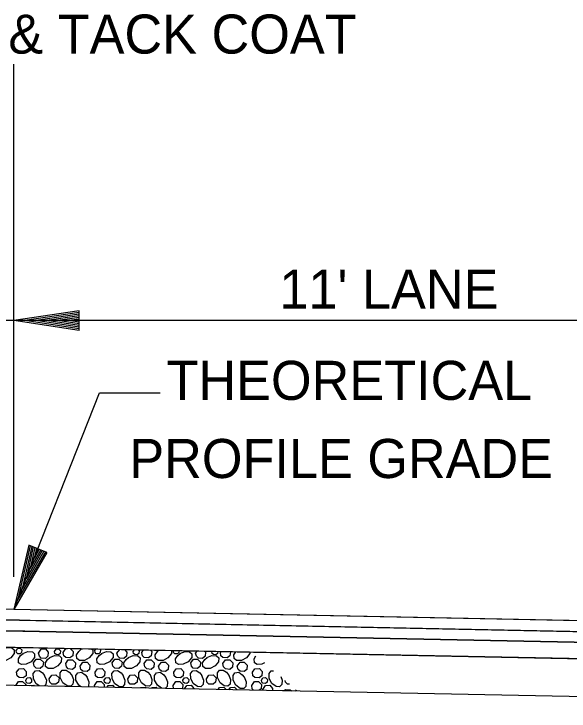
# Model space of a CAD drawing. Extents: x 2478 to 3210, y 439 to 841.
# Drawn here: x 2627.54 to 2644.6, y 587.29 to 608.7 of the extents above; entities that cross this region are included whole.
import ezdxf

# ---------------------------------------------------------------- set-up
doc = ezdxf.new("R2010")
doc.units = 0
for name, color, linetype in [('19', 7, 'Continuous'), ('R_Annotation', 7, 'Continuous'), ('R_Centerline', 7, 'Continuous'), ('R_Dimension', 7, 'Continuous')]:
    doc.layers.add(name, color=color, linetype=linetype)

msp = doc.modelspace()

# ---------------------------------------------------------------- linework, layer by layer
at = {"layer": '19'}
for points in [[(2601.503, 590.935), (2601.338, 590.605), (2605.378, 590.524), (2627.711, 590.078), (2649.713, 589.634), (2653.713, 589.474), (2653.543, 589.814), (2649.543, 589.974), (2627.543, 590.414)], [(2605.378, 590.524), (2605.212, 590.194), (2649.879, 589.301), (2649.713, 589.634)], [(2605.212, 590.194), (2604.965, 589.699), (2650.132, 588.796), (2649.879, 589.301)]]:
    msp.add_lwpolyline(points, close=True, dxfattribs=at)
at = {"layer": 'R_Annotation'}
for p, q in [((2627.543, 590.414), (2597.543, 591.014)), ((2627.711, 590.078), (2601.338, 590.605)), ((2649.543, 589.974), (2627.543, 590.414)), ((2627.879, 589.741), (2605.212, 590.194)), ((2649.713, 589.634), (2627.543, 590.081)), ((2628.132, 589.236), (2604.965, 589.699)), ((2649.879, 589.301), (2627.543, 589.748)), ((2650.132, 588.796), (2627.543, 589.247)), ((2666.995, 587.291), (2605.543, 588.52))]:
    msp.add_line(p, q, dxfattribs=at)
at = {"layer": 'R_Centerline'}
msp.add_line((2627.543, 591.415), (2627.543, 607.157), dxfattribs=at)
at = {"layer": 'R_Dimension'}
for p, q in [((2629.543, 599.581), (2627.543, 599.281)), ((2629.543, 599.531), (2627.877, 599.281)), ((2629.543, 599.48), (2628.221, 599.281)), ((2629.543, 599.43), (2628.554, 599.281)), ((2629.543, 598.981), (2629.543, 599.581)), ((2666.995, 599.281), (2586.003, 599.281)), ((2629.543, 598.981), (2627.543, 599.281)), ((2629.543, 599.031), (2627.877, 599.281)), ((2629.543, 599.082), (2628.221, 599.281)), ((2629.543, 599.132), (2628.554, 599.281)), ((2629.543, 599.379), (2628.893, 599.281)), ((2629.543, 599.184), (2628.893, 599.281)), ((2629.543, 599.328), (2629.227, 599.281)), ((2629.543, 599.234), (2629.227, 599.281)), ((2627.996, 592.385), (2627.543, 590.414)), ((2628.043, 592.367), (2627.665, 590.725)), ((2628.555, 592.165), (2627.996, 592.385)), ((2628.555, 592.165), (2627.543, 590.414)), ((2628.508, 592.184), (2627.665, 590.725)), ((2628.09, 592.348), (2627.791, 591.045)), ((2628.461, 592.202), (2627.791, 591.045)), ((2628.137, 592.33), (2627.913, 591.355)), ((2628.414, 592.221), (2627.913, 591.355)), ((2628.184, 592.311), (2628.037, 591.67)), ((2628.366, 592.24), (2628.037, 591.67)), ((2628.232, 592.292), (2628.16, 591.981)), ((2628.319, 592.258), (2628.16, 591.981)), ((2629.603, 589.187), (2629.648, 589.205)), ((2630.023, 589.152), (2630.058, 589.197)), ((2630.708, 589.067), (2630.791, 589.182)), ((2631.203, 589.117), (2631.241, 589.174)), ((2631.473, 589.092), (2631.521, 589.168)), ((2633.123, 589.067), (2633.172, 589.135)), ((2633.618, 589.117), (2633.624, 589.126)), ((2633.888, 589.092), (2633.906, 589.12)), ((2630.025, 588.031), (2630.018, 588.077)), ((2632.448, 587.982), (2632.433, 588.077)), ((2635.194, 587.927), (2635.188, 587.957)), ((2636.197, 587.907), (2636.221, 587.945))]:
    msp.add_line(p, q, dxfattribs=at)
for points in [[(2627.543, 590.414), (2630.17, 597.067), (2632.038, 597.067)], [(2627.188, 589.187), (2627.338, 589.247), (2627.478, 589.232), (2627.548, 589.167), (2627.548, 589.057), (2627.443, 588.927), (2627.293, 588.847), (2627.138, 588.847), (2627.063, 588.907), (2627.048, 589.017), (2627.123, 589.122), (2627.193, 589.187)], [(2627.608, 589.152), (2627.658, 589.217), (2627.733, 589.222), (2627.788, 589.167), (2627.778, 589.092), (2627.733, 589.047), (2627.658, 589.052), (2627.618, 589.092), (2627.608, 589.152)], [(2628.293, 589.067), (2628.383, 589.192), (2628.508, 589.197), (2628.598, 589.102), (2628.583, 588.977), (2628.508, 588.907), (2628.378, 588.917), (2628.323, 588.977), (2628.293, 589.067)], [(2628.788, 589.117), (2628.838, 589.192), (2628.913, 589.197), (2628.973, 589.137), (2628.963, 589.057), (2628.913, 589.017), (2628.838, 589.032), (2628.803, 589.057), (2628.788, 589.117)], [(2629.058, 589.092), (2629.133, 589.212), (2629.191, 589.214)], [(2629.273, 589.213), (2629.363, 589.117), (2629.348, 588.992), (2629.263, 588.927), (2629.133, 588.932), (2629.073, 588.992), (2629.058, 589.092)], [(2629.929, 589.2), (2629.963, 589.167), (2629.963, 589.057), (2629.858, 588.927), (2629.708, 588.847), (2629.553, 588.847), (2629.478, 588.907), (2629.463, 589.017), (2629.538, 589.122), (2629.608, 589.187)], [(2630.176, 589.195), (2630.203, 589.167), (2630.193, 589.092), (2630.148, 589.047), (2630.073, 589.052), (2630.033, 589.092), (2630.023, 589.152)], [(2630.94, 589.18), (2631.013, 589.102), (2630.998, 588.977), (2630.923, 588.907), (2630.793, 588.917), (2630.738, 588.977), (2630.708, 589.067)], [(2631.355, 589.171), (2631.388, 589.137), (2631.378, 589.057), (2631.328, 589.017), (2631.253, 589.032), (2631.218, 589.057), (2631.203, 589.117)], [(2631.734, 589.164), (2631.778, 589.117), (2631.763, 588.992), (2631.678, 588.927), (2631.548, 588.932), (2631.488, 588.992), (2631.473, 589.092)], [(2632.378, 589.151), (2632.378, 589.057), (2632.273, 588.927), (2632.123, 588.847), (2631.968, 588.847), (2631.893, 588.907), (2631.878, 589.017), (2631.953, 589.122), (2631.992, 589.158)], [(2632.616, 589.146), (2632.608, 589.092), (2632.563, 589.047), (2632.488, 589.052), (2632.448, 589.092), (2632.439, 589.15)], [(2627.813, 589.057), (2627.968, 589.117), (2628.108, 589.107), (2628.173, 589.047), (2628.173, 588.932), (2628.068, 588.807), (2627.913, 588.727), (2627.773, 588.722), (2627.683, 588.777), (2627.678, 588.892), (2627.743, 589.002), (2627.823, 589.062)], [(2628.643, 588.937), (2628.793, 588.997), (2628.938, 588.987), (2629.003, 588.922), (2628.998, 588.807), (2628.893, 588.677), (2628.743, 588.602), (2628.593, 588.602), (2628.513, 588.657), (2628.508, 588.772), (2628.573, 588.877), (2628.648, 588.937)], [(2630.228, 589.057), (2630.383, 589.117), (2630.523, 589.107), (2630.588, 589.047), (2630.588, 588.932), (2630.483, 588.807), (2630.328, 588.727), (2630.188, 588.722), (2630.098, 588.777), (2630.093, 588.892), (2630.158, 589.002), (2630.238, 589.062)], [(2631.058, 588.937), (2631.208, 588.997), (2631.353, 588.987), (2631.418, 588.922), (2631.413, 588.807), (2631.308, 588.677), (2631.158, 588.602), (2631.008, 588.602), (2630.928, 588.657), (2630.923, 588.772), (2630.988, 588.877), (2631.063, 588.937)], [(2632.643, 589.057), (2632.798, 589.117), (2632.938, 589.107), (2633.003, 589.047), (2633.003, 588.932), (2632.898, 588.807), (2632.743, 588.727), (2632.603, 588.722), (2632.513, 588.777), (2632.508, 588.892), (2632.573, 589.002), (2632.653, 589.062)], [(2633.402, 589.13), (2633.428, 589.102), (2633.413, 588.977), (2633.338, 588.907), (2633.208, 588.917), (2633.153, 588.977), (2633.123, 589.067)], [(2633.473, 588.937), (2633.623, 588.997), (2633.768, 588.987), (2633.833, 588.922), (2633.828, 588.807), (2633.723, 588.677), (2633.573, 588.602), (2633.423, 588.602), (2633.343, 588.657), (2633.338, 588.772), (2633.403, 588.877), (2633.478, 588.937)], [(2633.802, 589.122), (2633.793, 589.057), (2633.743, 589.017), (2633.668, 589.032), (2633.633, 589.057), (2633.618, 589.117)], [(2634.193, 589.114), (2634.178, 588.992), (2634.093, 588.927), (2633.963, 588.932), (2633.903, 588.992), (2633.888, 589.092)], [(2634.793, 589.102), (2634.793, 589.057), (2634.688, 588.927), (2634.538, 588.847), (2634.383, 588.847), (2634.308, 588.907), (2634.293, 589.017), (2634.36, 589.111)], [(2635.236, 588.767), (2635.158, 588.727), (2635.018, 588.722), (2634.928, 588.777), (2634.923, 588.892), (2634.977, 588.983)], [(2628.143, 588.767), (2628.228, 588.882), (2628.353, 588.887), (2628.448, 588.797), (2628.433, 588.667), (2628.348, 588.602), (2628.223, 588.612), (2628.163, 588.667), (2628.143, 588.767)], [(2629.133, 588.747), (2629.213, 588.862), (2629.343, 588.867), (2629.433, 588.772), (2629.423, 588.642), (2629.343, 588.572), (2629.213, 588.587), (2629.153, 588.647), (2629.133, 588.747)], [(2629.573, 588.672), (2629.663, 588.792), (2629.788, 588.797), (2629.878, 588.702), (2629.868, 588.572), (2629.788, 588.507), (2629.658, 588.512), (2629.598, 588.572), (2629.573, 588.672)], [(2630.558, 588.767), (2630.643, 588.882), (2630.768, 588.887), (2630.863, 588.797), (2630.848, 588.667), (2630.763, 588.602), (2630.638, 588.612), (2630.578, 588.667), (2630.558, 588.767)], [(2631.548, 588.747), (2631.628, 588.862), (2631.758, 588.867), (2631.848, 588.772), (2631.838, 588.642), (2631.758, 588.572), (2631.628, 588.587), (2631.568, 588.647), (2631.548, 588.747)], [(2631.988, 588.672), (2632.078, 588.792), (2632.203, 588.797), (2632.293, 588.702), (2632.283, 588.572), (2632.203, 588.507), (2632.073, 588.512), (2632.013, 588.572), (2631.988, 588.672)], [(2632.973, 588.767), (2633.058, 588.882), (2633.183, 588.887), (2633.278, 588.797), (2633.263, 588.667), (2633.178, 588.602), (2633.053, 588.612), (2632.993, 588.667), (2632.973, 588.767)], [(2633.963, 588.747), (2634.043, 588.862), (2634.173, 588.867), (2634.263, 588.772), (2634.253, 588.642), (2634.173, 588.572), (2634.043, 588.587), (2633.983, 588.647), (2633.963, 588.747)], [(2634.403, 588.672), (2634.493, 588.792), (2634.618, 588.797), (2634.708, 588.702), (2634.698, 588.572), (2634.618, 588.507), (2634.488, 588.512), (2634.428, 588.572), (2634.403, 588.672)], [(2627.623, 588.482), (2627.698, 588.592), (2627.838, 588.602), (2627.923, 588.507), (2627.913, 588.377), (2627.828, 588.312), (2627.698, 588.322), (2627.638, 588.377), (2627.623, 588.482)], [(2628.318, 588.065), (2628.218, 588.137), (2628.143, 588.292), (2628.138, 588.442), (2628.203, 588.527), (2628.313, 588.532), (2628.423, 588.462), (2628.483, 588.387)], [(2629.308, 588.417), (2629.368, 588.262), (2629.353, 588.122), (2629.288, 588.052), (2629.173, 588.062), (2629.048, 588.162), (2628.963, 588.317), (2628.963, 588.462), (2629.023, 588.547), (2629.143, 588.552), (2629.243, 588.487), (2629.308, 588.407)], [(2630.038, 588.482), (2630.113, 588.592), (2630.253, 588.602), (2630.338, 588.507), (2630.328, 588.377), (2630.243, 588.312), (2630.113, 588.322), (2630.053, 588.377), (2630.038, 588.482)], [(2630.888, 588.392), (2630.953, 588.242), (2630.938, 588.102), (2630.873, 588.037), (2630.763, 588.042), (2630.633, 588.137), (2630.558, 588.292), (2630.553, 588.442), (2630.618, 588.527), (2630.728, 588.532), (2630.838, 588.462), (2630.898, 588.387)], [(2631.723, 588.417), (2631.783, 588.262), (2631.768, 588.122), (2631.703, 588.052), (2631.588, 588.062), (2631.463, 588.162), (2631.378, 588.317), (2631.378, 588.462), (2631.438, 588.547), (2631.558, 588.552), (2631.658, 588.487), (2631.723, 588.407)], [(2632.453, 588.482), (2632.528, 588.592), (2632.668, 588.602), (2632.753, 588.507), (2632.743, 588.377), (2632.658, 588.312), (2632.528, 588.322), (2632.468, 588.377), (2632.453, 588.482)], [(2633.303, 588.392), (2633.368, 588.242), (2633.353, 588.102), (2633.288, 588.037), (2633.178, 588.042), (2633.048, 588.137), (2632.973, 588.292), (2632.968, 588.442), (2633.033, 588.527), (2633.143, 588.532), (2633.253, 588.462), (2633.313, 588.387)], [(2634.138, 588.417), (2634.198, 588.262), (2634.183, 588.122), (2634.118, 588.052), (2634.003, 588.062), (2633.878, 588.162), (2633.793, 588.317), (2633.793, 588.462), (2633.853, 588.547), (2633.973, 588.552), (2634.073, 588.487), (2634.138, 588.407)], [(2634.868, 588.482), (2634.943, 588.592), (2635.083, 588.602), (2635.168, 588.507), (2635.158, 588.377), (2635.073, 588.312), (2634.943, 588.322), (2634.883, 588.377), (2634.868, 588.482)], [(2635.737, 588.349), (2635.783, 588.242), (2635.768, 588.102), (2635.703, 588.037), (2635.593, 588.042), (2635.463, 588.137), (2635.388, 588.292), (2635.383, 588.442), (2635.448, 588.527), (2635.52, 588.531)], [(2627.903, 588.242), (2627.948, 588.312), (2628.028, 588.317), (2628.083, 588.262), (2628.078, 588.182), (2628.028, 588.137), (2627.948, 588.147), (2627.913, 588.182), (2627.903, 588.242)], [(2628.473, 588.392), (2628.538, 588.242), (2628.523, 588.102), (2628.483, 588.061)], [(2628.623, 588.277), (2628.703, 588.392), (2628.833, 588.402), (2628.928, 588.312), (2628.908, 588.182), (2628.833, 588.117), (2628.703, 588.122), (2628.643, 588.182), (2628.623, 588.277)], [(2629.594, 588.039), (2629.533, 588.087), (2629.448, 588.242), (2629.448, 588.387), (2629.503, 588.467), (2629.618, 588.482), (2629.728, 588.407), (2629.788, 588.332)], [(2629.783, 588.342), (2629.843, 588.187), (2629.833, 588.047), (2629.822, 588.035)], [(2630.318, 588.242), (2630.363, 588.312), (2630.443, 588.317), (2630.498, 588.262), (2630.493, 588.182), (2630.443, 588.137), (2630.363, 588.147), (2630.328, 588.182), (2630.318, 588.242)], [(2631.038, 588.277), (2631.118, 588.392), (2631.248, 588.402), (2631.343, 588.312), (2631.323, 588.182), (2631.248, 588.117), (2631.118, 588.122), (2631.058, 588.182), (2631.038, 588.277)], [(2632.071, 587.99), (2631.948, 588.087), (2631.863, 588.242), (2631.863, 588.387), (2631.918, 588.467), (2632.033, 588.482), (2632.143, 588.407), (2632.203, 588.332)], [(2632.198, 588.342), (2632.258, 588.187), (2632.248, 588.047), (2632.193, 587.987)], [(2632.733, 588.242), (2632.778, 588.312), (2632.858, 588.317), (2632.913, 588.262), (2632.908, 588.182), (2632.858, 588.137), (2632.778, 588.147), (2632.743, 588.182), (2632.733, 588.242)], [(2633.453, 588.277), (2633.533, 588.392), (2633.663, 588.402), (2633.758, 588.312), (2633.738, 588.182), (2633.663, 588.117), (2633.533, 588.122), (2633.473, 588.182), (2633.453, 588.277)], [(2634.613, 588.342), (2634.673, 588.187), (2634.663, 588.047), (2634.603, 587.982), (2634.488, 587.987), (2634.363, 588.087), (2634.278, 588.242), (2634.278, 588.387), (2634.333, 588.467), (2634.448, 588.482), (2634.558, 588.407), (2634.618, 588.332)], [(2635.148, 588.242), (2635.193, 588.312), (2635.273, 588.317), (2635.328, 588.262), (2635.323, 588.182), (2635.273, 588.137), (2635.193, 588.147), (2635.158, 588.182), (2635.148, 588.242)], [(2627.605, 588.079), (2627.683, 588.197), (2627.808, 588.202), (2627.903, 588.102), (2627.901, 588.073)], [(2628.019, 588.071), (2628.023, 588.077), (2628.158, 588.087), (2628.175, 588.068)], [(2630.018, 588.077), (2630.098, 588.197), (2630.223, 588.202), (2630.318, 588.102), (2630.312, 588.025)], [(2630.402, 588.023), (2630.438, 588.077), (2630.573, 588.087), (2630.632, 588.018)], [(2632.433, 588.077), (2632.513, 588.197), (2632.638, 588.202), (2632.733, 588.102), (2632.723, 587.977), (2632.723, 587.977)], [(2632.785, 587.975), (2632.853, 588.077), (2632.988, 588.087), (2633.073, 587.987), (2633.071, 587.97)], [(2634.848, 588.077), (2634.928, 588.197), (2635.053, 588.202), (2635.148, 588.102), (2635.138, 587.977), (2635.077, 587.93)], [(2634.904, 587.933), (2634.863, 587.977), (2634.848, 588.077)], [(2635.188, 587.957), (2635.268, 588.077), (2635.403, 588.087), (2635.488, 587.987), (2635.481, 587.921)], [(2636.012, 588.12), (2635.948, 588.122), (2635.888, 588.182), (2635.878, 588.232)], [(2631.429, 588.003), (2631.438, 588.017), (2631.573, 588.022), (2631.598, 587.999)], [(2631.77, 587.996), (2631.783, 588.012), (2631.908, 588.022), (2631.938, 587.992)], [(2633.813, 587.955), (2633.853, 588.017), (2633.988, 588.022), (2634.065, 587.95)], [(2634.148, 587.948), (2634.198, 588.012), (2634.323, 588.022), (2634.403, 587.943)], [(2635.8, 587.915), (2635.893, 587.952), (2636.028, 587.942), (2636.064, 587.91)]]:
    msp.add_lwpolyline(points, dxfattribs=at)

# ---------------------------------------------------------------- texts
at = {"layer": 'R_Annotation'}
for s, p in [('330 LBS. PER SQ. YD. & TACK COAT', (2610.246, 607.481)), ("11' LANE", (2635.697, 599.649)), ('THEORETICAL ', (2632.229, 596.847)), ('PROFILE GRADE', (2631.086, 594.447))]:
    msp.add_text(s, height=1.2, dxfattribs=at).set_placement(p)

doc.saveas('drawing.dxf')
